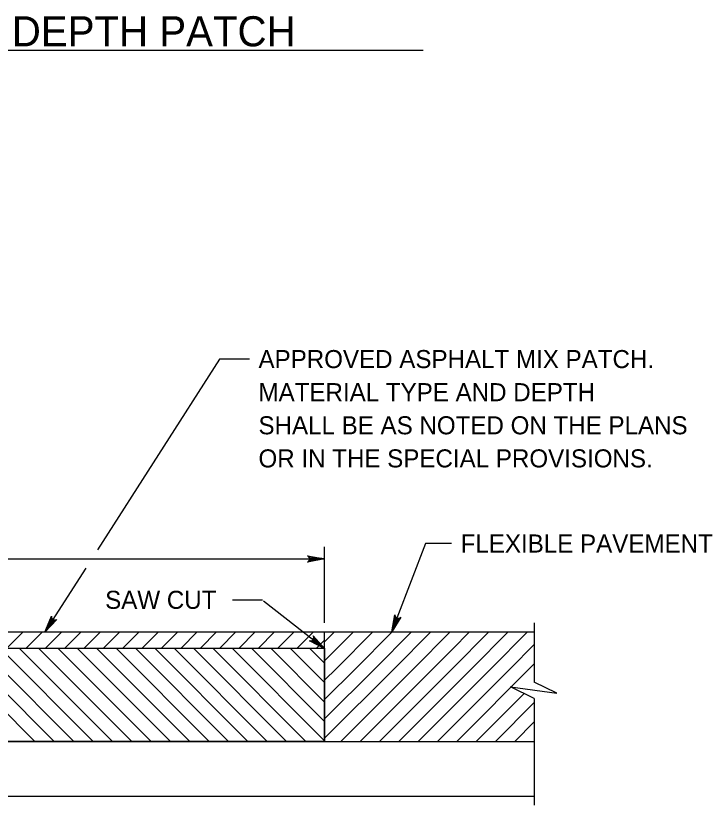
# Model space of a CAD drawing. Extents: x 3.47 to 10.73, y 1.11 to 10.92.
# Drawn here: x 7.328 to 9.643, y 5.67 to 8.293 of the extents above; entities that cross this region are included whole.
import ezdxf

# ---------------------------------------------------------------- set-up
doc = ezdxf.new("R2010")
doc.units = 0
for name, color, linetype in [('DETL-DIMS', 7, 'Continuous'), ('DETL-LINE', 7, 'Continuous'), ('DETL-NOTE', 7, 'Continuous'), ('DETL-PATT', 7, 'Continuous'), ('DETL-TITL', 7, 'Continuous')]:
    doc.layers.add(name, color=color, linetype=linetype)

msp = doc.modelspace()

# ---------------------------------------------------------------- linework, layer by layer
at = {"layer": 'DETL-DIMS'}
for p, q in [((8.0048, 7.152), (7.599, 6.518)), ((8.1043, 7.152), (8.0048, 7.152)), ((8.6901, 6.5392), (8.595, 6.2911)), ((8.7765, 6.5392), (8.6901, 6.5392)), ((8.3545, 6.2756), (8.3545, 6.5283)), ((5.5666, 6.4877), (8.3545, 6.4877)), ((7.5602, 6.4574), (7.4291, 6.2526)), ((8.0486, 6.3521), (8.148, 6.3521)), ((8.1512, 6.349), (8.3541, 6.1898))]:
    msp.add_line(p, q, dxfattribs=at)
for points in [[(8.3545, 6.4877), (8.298, 6.4772), (8.3024, 6.4802), (8.3046, 6.484), (8.3053, 6.4877), (8.3046, 6.4915), (8.3024, 6.4953), (8.298, 6.4983), (8.3545, 6.4877), (8.3024, 6.4953), (8.3046, 6.4915), (8.3545, 6.4877), (8.3053, 6.4877), (8.3046, 6.484), (8.3545, 6.4877), (8.3024, 6.4802)], [(7.4248, 6.2448), (7.4463, 6.2981), (7.4465, 6.2928), (7.4485, 6.2888), (7.4513, 6.2862), (7.4548, 6.2847), (7.4592, 6.2846), (7.4641, 6.2866), (7.4248, 6.2448), (7.4592, 6.2846), (7.4548, 6.2847), (7.4248, 6.2448), (7.4513, 6.2862), (7.4485, 6.2888), (7.4248, 6.2448), (7.4465, 6.2928)], [(8.5776, 6.2452), (8.5879, 6.3017), (8.5892, 6.2965), (8.5919, 6.2931), (8.5952, 6.2911), (8.599, 6.2904), (8.6033, 6.2911), (8.6077, 6.2941), (8.5776, 6.2452), (8.6033, 6.2911), (8.599, 6.2904), (8.5776, 6.2452), (8.5952, 6.2911), (8.5919, 6.2931), (8.5776, 6.2452), (8.5892, 6.2965)], [(8.3547, 6.1895), (8.3037, 6.216), (8.309, 6.2157), (8.3131, 6.2173), (8.3159, 6.2199), (8.3178, 6.2232), (8.3183, 6.2276), (8.3168, 6.2327), (8.3547, 6.1895), (8.3183, 6.2276), (8.3178, 6.2232), (8.3547, 6.1895), (8.3159, 6.2199), (8.3131, 6.2173), (8.3547, 6.1895), (8.309, 6.2157)]]:
    msp.add_lwpolyline(points, dxfattribs=at)
at = {"layer": 'DETL-LINE'}
for p, q in [((9.0515, 6.2756), (9.0515, 6.0778)), ((4.8696, 6.2453), (9.0515, 6.2453)), ((8.3545, 5.8817), (8.3545, 6.2453)), ((9.0515, 6.0245), (9.0515, 5.6696)), ((5.5666, 5.8817), (8.3545, 5.8817)), ((8.3545, 5.8817), (9.0515, 5.8817)), ((4.8696, 5.6999), (9.0515, 5.6999))]:
    msp.add_line(p, q, dxfattribs=at)
msp.add_lwpolyline([(5.5666, 6.1914), (8.3545, 6.1914), (8.3545, 5.8817), (5.5666, 5.8817)], close=True, dxfattribs=at)
msp.add_lwpolyline([(9.0513, 6.0246), (8.9727, 6.063), (9.1265, 6.0421), (9.0513, 6.0779)], dxfattribs=at)
at = {"layer": 'DETL-NOTE'}
msp.add_line((5.257, 8.1787), (8.682, 8.1787), dxfattribs=at)
at = {"layer": 'DETL-PATT'}
for p, q in [((7.2979, 6.1914), (7.3518, 6.2453)), ((7.3622, 6.1914), (7.4162, 6.2453)), ((7.4266, 6.1914), (7.4805, 6.2453)), ((7.4909, 6.1914), (7.5449, 6.2453)), ((7.5553, 6.1914), (7.6092, 6.2453)), ((7.6196, 6.1914), (7.6735, 6.2453)), ((7.684, 6.1914), (7.7379, 6.2453)), ((7.7483, 6.1914), (7.8022, 6.2453)), ((7.8127, 6.1914), (7.8666, 6.2453)), ((7.877, 6.1914), (7.9309, 6.2453)), ((7.9414, 6.1914), (7.9953, 6.2453)), ((8.0057, 6.1914), (8.0596, 6.2453)), ((8.07, 6.1914), (8.124, 6.2453)), ((8.1344, 6.1914), (8.1883, 6.2453)), ((8.1987, 6.1914), (8.2527, 6.2453)), ((8.2631, 6.1914), (8.317, 6.2453)), ((8.3532, 6.2112), (8.3878, 6.2459)), ((8.3545, 6.1491), (8.4507, 6.2453)), ((8.3935, 6.1238), (8.515, 6.2453)), ((8.522, 6.1238), (8.6436, 6.2453)), ((8.5863, 6.1238), (8.7078, 6.2453)), ((8.6506, 6.1238), (8.7721, 6.2453)), ((8.7792, 6.1881), (8.8364, 6.2453)), ((8.7792, 6.1238), (8.9007, 6.2453)), ((8.8435, 6.1238), (8.965, 6.2453)), ((8.9077, 6.1238), (9.0292, 6.2453)), ((8.3274, 6.1914), (8.3545, 6.2185)), ((8.4578, 6.1238), (8.577, 6.243)), ((5.5666, 6.1914), (8.3545, 6.1914)), ((7.0818, 6.1914), (7.3915, 5.8817)), ((7.1461, 6.1914), (7.4558, 5.8817)), ((7.2104, 6.1914), (7.5202, 5.8817)), ((7.2748, 6.1914), (7.5845, 5.8817)), ((7.3391, 6.1914), (7.6488, 5.8817)), ((7.4035, 6.1914), (7.7132, 5.8817)), ((7.4678, 6.1914), (7.7775, 5.8817)), ((7.5322, 6.1914), (7.8419, 5.8817)), ((7.5965, 6.1914), (7.9062, 5.8817)), ((7.6609, 6.1914), (7.9706, 5.8817)), ((7.7252, 6.1914), (8.0349, 5.8817)), ((7.7896, 6.1914), (8.0993, 5.8817)), ((7.8539, 6.1914), (8.1636, 5.8817)), ((7.9183, 6.1914), (8.228, 5.8817)), ((7.9826, 6.1914), (8.2923, 5.8817)), ((8.047, 6.1914), (8.3545, 5.8838)), ((8.1113, 6.1914), (8.3545, 5.9482)), ((8.1756, 6.1914), (8.3545, 6.0125)), ((8.24, 6.1914), (8.3545, 6.0769)), ((8.3043, 6.1914), (8.3545, 6.1412)), ((8.972, 6.1238), (9.0515, 6.2033)), ((8.7149, 6.1238), (8.7792, 6.1881)), ((8.7942, 5.8817), (9.0515, 6.139)), ((8.3545, 5.9563), (8.522, 6.1238)), ((8.3545, 5.892), (8.5863, 6.1238)), ((8.3545, 6.0848), (8.3935, 6.1238)), ((8.3545, 6.0205), (8.4578, 6.1238)), ((8.4085, 5.8817), (8.6506, 6.1238)), ((8.4728, 5.8817), (8.7149, 6.1238)), ((8.537, 5.8817), (8.7792, 6.1238)), ((8.7792, 6.0595), (8.8435, 6.1238)), ((8.7792, 5.9952), (8.9077, 6.1238)), ((8.7792, 5.931), (8.972, 6.1238)), ((8.6013, 5.8817), (8.7792, 6.0595)), ((8.8585, 5.8817), (9.0177, 6.041)), ((8.9227, 5.8817), (9.0515, 6.0104)), ((8.6656, 5.8817), (8.7792, 5.9952)), ((8.7299, 5.8817), (8.7792, 5.931)), ((8.987, 5.8817), (9.0515, 5.9461))]:
    msp.add_line(p, q, dxfattribs=at)

# ---------------------------------------------------------------- texts
at = {"layer": 'DETL-NOTE'}
for s, p in [('APPROVED ASPHALT MIX PATCH.', (8.1346, 7.122)), ('MATERIAL TYPE AND DEPTH', (8.1346, 7.012)), ('SHALL BE AS NOTED ON THE PLANS', (8.1346, 6.902)), ('OR IN THE SPECIAL PROVISIONS.', (8.1346, 6.792)), ('FLEXIBLE PAVEMENT', (8.8068, 6.5092)), ('SAW CUT', (7.6248, 6.3221))]:
    msp.add_text(s, height=0.06, dxfattribs=at).set_placement(p)
at = {"layer": 'DETL-TITL'}
msp.add_text('COMPOSITE PAVEMENT - FULL DEPTH PATCH', height=0.1, dxfattribs=at).set_placement((5.2563, 8.1912))

doc.saveas('drawing.dxf')
